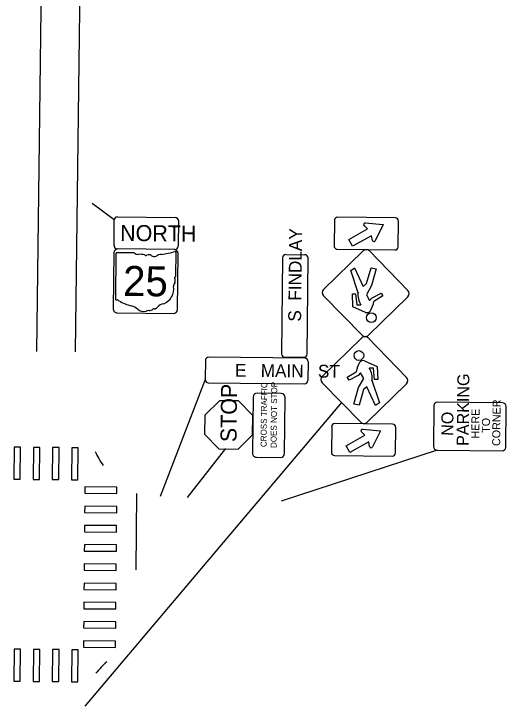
# Model space of a CAD drawing. Extents: x 1652376 to 1652707, y 605933 to 608571.
# Drawn here: x 1652553.2 to 1652706.7, y 606825.9 to 607041.8 of the extents above; entities that cross this region are included whole.
import ezdxf

# ---------------------------------------------------------------- set-up
doc = ezdxf.new("R2010")
doc.units = 0
for name, color, linetype in [('_CIVIL_CONSTRUCTION', 7, 'Continuous'), ('GE_P_Alignment', 7, 'Continuous'), ('PM_P_CL_Double_Solid', 7, 'Continuous'), ('SH_Border', 7, 'Continuous'), ('SN_X_Public', 7, 'Continuous'), ('UT_X_Misc_Cells', 7, 'Continuous')]:
    doc.layers.add(name, color=color, linetype=linetype)

msp = doc.modelspace()

# ---------------------------------------------------------------- linework, layer by layer
at = {"layer": '_CIVIL_CONSTRUCTION'}
for points in [[(1652553.24, 606896.7), (1652555.24, 606896.68), (1652555.33, 606906.68), (1652553.33, 606906.7)], [(1652559.24, 606896.65), (1652561.24, 606896.63), (1652561.33, 606906.63), (1652559.33, 606906.64)], [(1652565.24, 606896.59), (1652567.24, 606896.58), (1652567.33, 606906.58), (1652565.33, 606906.59)], [(1652571.24, 606896.54), (1652573.24, 606896.53), (1652573.33, 606906.53), (1652571.33, 606906.54)], [(1652575.38, 606894.32), (1652575.37, 606892.32), (1652585.37, 606892.23), (1652585.38, 606894.23)], [(1652575.33, 606888.32), (1652575.32, 606886.32), (1652585.32, 606886.23), (1652585.33, 606888.23)], [(1652575.33, 606888.32), (1652575.32, 606886.32), (1652585.32, 606886.23), (1652585.33, 606888.23)], [(1652575.28, 606882.32), (1652575.27, 606880.32), (1652585.27, 606880.23), (1652585.28, 606882.23)], [(1652575.23, 606876.32), (1652575.21, 606874.32), (1652585.21, 606874.23), (1652585.23, 606876.23)], [(1652575.18, 606870.32), (1652575.16, 606868.32), (1652585.16, 606868.24), (1652585.18, 606870.24)], [(1652575.13, 606864.32), (1652575.11, 606862.32), (1652585.11, 606862.24), (1652585.13, 606864.24)], [(1652575.08, 606858.32), (1652575.06, 606856.32), (1652585.06, 606856.24), (1652585.08, 606858.24)], [(1652575.03, 606852.32), (1652575.01, 606850.32), (1652585.01, 606850.24), (1652585.03, 606852.24)], [(1652574.98, 606846.32), (1652574.96, 606844.32), (1652584.96, 606844.24), (1652584.98, 606846.24)], [(1652553.24, 606833.7), (1652555.24, 606833.68), (1652555.33, 606843.68), (1652553.33, 606843.7)], [(1652559.24, 606833.65), (1652561.24, 606833.63), (1652561.33, 606843.63), (1652559.33, 606843.64)], [(1652565.24, 606833.59), (1652567.24, 606833.58), (1652567.33, 606843.58), (1652565.33, 606843.59)], [(1652571.24, 606833.54), (1652573.24, 606833.53), (1652573.33, 606843.53), (1652571.33, 606843.54)]]:
    msp.add_lwpolyline(points, close=True, dxfattribs=at)
at = {"layer": 'GE_P_Alignment'}
msp.add_lwpolyline([(1652560.46, 606936.56), (1652563.76, 607199.19), (1652564.08, 607225.34)], dxfattribs=at)
at = {"layer": 'PM_P_CL_Double_Solid'}
msp.add_lwpolyline([(1652572.46, 606936.42), (1652575.76, 607199.05), (1652576.07, 607225.19)], dxfattribs=at)
for centre, start, end in [((1652603.12, 606916.64), 204.7562, 215.3046), ((1652600.15, 606819.63), 131.6839, 142.1561)]:
    msp.add_arc(centre, 27, start, end, dxfattribs=at)
at = {"layer": 'SH_Border'}
for p, q in [((1652584.48, 606969.57), (1652584.57, 606977.57)), ((1652585.58, 606978.56), (1652603.58, 606978.36)), ((1652604.57, 606977.35), (1652604.48, 606969.35)), ((1652663.54, 606974.78), (1652662.45, 606975.79)), ((1652662.83, 606976.63), (1652662.83, 606976.63)), ((1652657.68, 606971.47), (1652663.54, 606974.78)), ((1652658.87, 606969.36), (1652657.68, 606971.47)), ((1652664.74, 606972.66), (1652658.87, 606969.36)), ((1652665.03, 606971.21), (1652664.74, 606972.66)), ((1652585.07, 606967.12), (1652584.91, 606952.89)), ((1652590.74, 606967.3), (1652585.25, 606967.36)), ((1652603.47, 606968.36), (1652585.47, 606968.56)), ((1652603.74, 606960.07), (1652603.82, 606967.51)), ((1652658.29, 606961.83), (1652659.49, 606962.68)), ((1652659.49, 606962.68), (1652662.2, 606956.85)), ((1652663.2, 606957.71), (1652664.64, 606962.63)), ((1652664.64, 606962.63), (1652666.22, 606962.32)), ((1652666.22, 606962.32), (1652664.78, 606957.11)), ((1652660.59, 606954.83), (1652658.29, 606961.83)), ((1652603.74, 606960.07), (1652603.74, 606960.07)), ((1652662.2, 606956.85), (1652663.2, 606957.71)), ((1652664.78, 606957.11), (1652663.16, 606954.22)), ((1652658.96, 606950.49), (1652658.81, 606954.56)), ((1652658.81, 606954.56), (1652659.8, 606954.55)), ((1652659.8, 606954.55), (1652660.15, 606951.06)), ((1652663.16, 606954.22), (1652664.13, 606952.47)), ((1652664.93, 606953.33), (1652667.72, 606954.75)), ((1652668.3, 606953.87), (1652665.51, 606952.16)), ((1652667.72, 606954.75), (1652668.3, 606953.87)), ((1652664.13, 606952.47), (1652664.93, 606953.33)), ((1652662.9, 606948.71), (1652658.96, 606950.49)), ((1652660.15, 606951.06), (1652661.46, 606951.05)), ((1652662.6, 606933.68), (1652666.54, 606931.89)), ((1652657.2, 606928.51), (1652659.99, 606930.23)), ((1652661.37, 606929.92), (1652660.57, 606929.06)), ((1652662.34, 606928.16), (1652661.37, 606929.92)), ((1652665.35, 606931.33), (1652664.04, 606931.34)), ((1652665.7, 606927.84), (1652665.35, 606931.33)), ((1652666.54, 606931.89), (1652666.69, 606927.83)), ((1652657.78, 606927.63), (1652657.2, 606928.51)), ((1652660.57, 606929.06), (1652657.78, 606927.63)), ((1652660.73, 606925.28), (1652662.34, 606928.16)), ((1652666.69, 606927.83), (1652665.7, 606927.84)), ((1652663.3, 606925.54), (1652662.3, 606924.68)), ((1652666.01, 606919.71), (1652663.3, 606925.54)), ((1652664.91, 606927.56), (1652667.21, 606920.56)), ((1652659.28, 606920.07), (1652660.73, 606925.28)), ((1652662.3, 606924.68), (1652660.86, 606919.76)), ((1652617.32, 606921.18), (1652612.77, 606916.73)), ((1652623.31, 606921.12), (1652617.32, 606921.18)), ((1652627.77, 606916.57), (1652623.31, 606921.12)), ((1652660.86, 606919.76), (1652659.28, 606920.07)), ((1652667.21, 606920.56), (1652666.01, 606919.71)), ((1652612.77, 606916.73), (1652612.7, 606910.73)), ((1652627.7, 606910.57), (1652627.77, 606916.57)), ((1652704.39, 606913.02), (1652704.39, 606913.02)), ((1652612.7, 606910.73), (1652617.15, 606906.18)), ((1652623.15, 606906.12), (1652627.7, 606910.57)), ((1652656.83, 606907.15), (1652662.69, 606910.46)), ((1652662.69, 606910.46), (1652661.6, 606911.46)), ((1652663.89, 606908.34), (1652658.02, 606905.04)), ((1652664.18, 606906.88), (1652663.89, 606908.34)), ((1652617.15, 606906.18), (1652623.15, 606906.12)), ((1652658.02, 606905.04), (1652656.83, 606907.15))]:
    msp.add_line(p, q, dxfattribs=at)
for points in [[(1652653.18, 606977.43), (1652653.1, 606969.43)], [(1652672.19, 606978.22), (1652654.19, 606978.42)], [(1652662.83, 606976.63), (1652668.44, 606976.14), (1652665.95, 606971.09)], [(1652673.09, 606969.21), (1652673.18, 606977.21)], [(1652584.46, 606967.32), (1652584.26, 606949.82)], [(1652603.22, 606968.36), (1652585.72, 606968.55)], [(1652604.26, 606949.6), (1652604.46, 606967.1)], [(1652638.02, 606966.79), (1652644.02, 606966.73)], [(1652649.82, 606955.89), (1652662.11, 606967.92)], [(1652654.09, 606968.42), (1652672.08, 606968.22)], [(1652664.09, 606967.9), (1652676.12, 606955.6)], [(1652637.01, 606965.81), (1652636.68, 606935.81)], [(1652644.68, 606935.72), (1652645.01, 606965.72)], [(1652661.82, 606941.62), (1652649.8, 606953.91)], [(1652676.1, 606953.62), (1652663.8, 606941.59)], [(1652585.5, 606948.56), (1652603, 606948.36)], [(1652649.4, 606928.77), (1652661.7, 606940.79)], [(1652663.68, 606940.77), (1652675.71, 606928.48)], [(1652643.97, 606934.46), (1652613.97, 606934.79)], [(1652637.67, 606934.8), (1652643.67, 606934.73)], [(1652612.96, 606933.8), (1652612.89, 606927.8)], [(1652644.96, 606933.45), (1652644.89, 606927.45)], [(1652613.88, 606926.79), (1652643.88, 606926.46)], [(1652661.41, 606914.49), (1652649.38, 606926.79)], [(1652675.68, 606926.5), (1652663.39, 606914.47)], [(1652636.59, 606923.47), (1652629.09, 606923.55)], [(1652627.83, 606922.32), (1652627.64, 606904.82)], [(1652637.64, 606904.71), (1652637.83, 606922.21)], [(1652684.24, 606919.65), (1652684.1, 606906.9)], [(1652705.63, 606920.54), (1652685.38, 606920.76)], [(1652706.6, 606906.65), (1652706.74, 606919.4)], [(1652652.34, 606913.11), (1652652.25, 606905.11)], [(1652671.35, 606913.9), (1652653.35, 606914.09)], [(1652672.25, 606904.89), (1652672.33, 606912.89)], [(1652661.98, 606912.31), (1652667.6, 606911.82), (1652665.1, 606906.77)], [(1652653.24, 606904.1), (1652671.24, 606903.9)], [(1652685.21, 606905.76), (1652705.46, 606905.54)], [(1652628.87, 606903.55), (1652636.37, 606903.47)]]:
    msp.add_lwpolyline(points, dxfattribs=at)
for centre in [(1652664.68, 606947.1), (1652660.82, 606935.29)]:
    msp.add_circle(centre, 1.52, dxfattribs=at)
for centre, radius, start, end in [((1652585.57, 606977.56), 1, 89.3709, 179.3709), ((1652603.57, 606977.36), 1, 359.3709, 89.3709), ((1652654.18, 606977.42), 1, 89.3709, 179.3709), ((1652672.18, 606977.22), 1, 359.3709, 89.3709), ((1652662.78, 606976.14), 0.486, 85.0472, 227.1837), ((1652665.51, 606971.3), 0.486, 191.5581, 333.6946), ((1652585.48, 606969.56), 1, 179.3709, 269.3709), ((1652603.48, 606969.36), 1, 269.3709, 359.3709), ((1652654.09, 606969.42), 1, 179.3709, 269.3709), ((1652672.09, 606969.22), 1, 269.3709, 359.3709), ((1652585.71, 606967.3), 1.25, 89.3709, 179.3709), ((1652585.28, 606967.15), 0.217, 97.501, 187.501), ((1652592.07, 606968.94), 2.11, 230.9904, 270.4828), ((1652592.66, 606959.29), 7.56, 79.8576, 94.3592), ((1652594.46, 606967.12), 0.608, 219.163, 296.4733), ((1652595.34, 606965.47), 1.26, 53.8376, 118.512), ((1652599.63, 606962.86), 4, 96.7171, 120.1397), ((1652597.35, 606986.63), 19.88, 275.2154, 288.2773), ((1652603.21, 606967.11), 1.25, 359.3709, 89.3709), ((1652603.61, 606967.54), 0.209, 351.233, 97.1089), ((1652638.01, 606965.79), 1, 89.3709, 179.3709), ((1652644.01, 606965.73), 1, 359.3709, 89.3709), ((1652663.09, 606966.92), 1.4, 44.3709, 134.3709), ((1652596.99, 606967.7), 1.52, 233.2271, 294.1991), ((1652603.68, 606959.52), 0.323, 107.3149, 209.7079), ((1652601.62, 606958.6), 1.94, 339.4039, 23.0205), ((1652603.52, 606960.04), 0.223, 288.9747, 7.105), ((1652598.13, 606956.07), 4.97, 291.6798, 8.3567), ((1652604.45, 606956.94), 1.41, 136.1774, 186.3005), ((1652650.8, 606954.89), 1.4, 134.3709, 224.3709), ((1652666.17, 606954.16), 5.64, 171.2211, 213.4318), ((1652675.12, 606954.62), 1.4, 314.3709, 44.3709), ((1652585.13, 606952.86), 0.219, 171.3293, 257.6775), ((1652585.17, 606954.31), 1.67, 266.7099, 279.9748), ((1652585.49, 606952.06), 0.603, 29.1193, 92.6426), ((1652593.25, 606964.76), 14.36, 239.7838, 256.5694), ((1652655.98, 606953.95), 9.69, 330.912, 349.4026), ((1652585.51, 606949.81), 1.25, 179.3709, 269.3709), ((1652588.76, 606946.45), 4.49, 46.5551, 75.2069), ((1652593.68, 606951.9), 2.85, 230.0713, 285.6627), ((1652595.28, 606946.96), 2.34, 85.066, 110.5808), ((1652595.53, 606950.82), 1.52, 268.1479, 314.9202), ((1652596.88, 606949.42), 0.428, 65.1226, 132.0193), ((1652596.72, 606951.38), 1.61, 282.2441, 322.648), ((1652600.15, 606948.73), 2.72, 93.774, 141.9476), ((1652603.01, 606949.61), 1.25, 269.3709, 359.3709), ((1652663.27, 606950.16), 1.5, 255.615, 321.8659), ((1652662.68, 606939.79), 1.4, 44.3709, 134.3709), ((1652662.82, 606942.6), 1.4, 224.3709, 314.3709), ((1652613.96, 606933.79), 1, 89.3709, 179.3709), ((1652637.68, 606935.8), 1, 179.3709, 269.3709), ((1652643.68, 606935.73), 1, 269.3709, 359.3709), ((1652643.96, 606933.46), 1, 359.3709, 89.3709), ((1652669.52, 606928.44), 9.69, 150.912, 169.4026), ((1652662.23, 606932.23), 1.5, 75.615, 141.8659), ((1652659.33, 606928.23), 5.64, 351.2211, 33.4318), ((1652613.89, 606927.79), 1, 179.3709, 269.3709), ((1652650.38, 606927.77), 1.4, 134.3709, 224.3709), ((1652674.71, 606927.5), 1.4, 314.3709, 44.3709), ((1652643.89, 606927.46), 1, 269.3709, 359.3709), ((1652629.08, 606922.3), 1.25, 89.3709, 179.3709), ((1652636.58, 606922.22), 1.25, 359.3709, 89.3709), ((1652685.36, 606919.63), 1.12, 89.3709, 179.3709), ((1652705.61, 606919.41), 1.12, 359.3709, 89.3709), ((1652653.33, 606913.09), 1, 89.3709, 179.3709), ((1652662.41, 606915.47), 1.4, 224.3709, 314.3709), ((1652671.33, 606912.9), 1, 359.3709, 89.3709), ((1652661.94, 606911.82), 0.486, 85.0472, 227.1837), ((1652664.66, 606906.98), 0.486, 191.5581, 333.6946), ((1652685.22, 606906.88), 1.12, 179.3709, 269.3709), ((1652705.47, 606906.66), 1.12, 269.3709, 359.3709), ((1652628.89, 606904.8), 1.25, 179.3709, 269.3709), ((1652636.39, 606904.72), 1.25, 269.3709, 359.3709), ((1652653.25, 606905.1), 1, 179.3709, 269.3709), ((1652671.25, 606904.9), 1, 269.3709, 359.3709)]:
    msp.add_arc(centre, radius, start, end, dxfattribs=at)
at = {"layer": 'SN_X_Public'}
msp.add_line((1652591.4, 606868.48), (1652591.6, 606892.22), dxfattribs=at)
at = {"layer": 'UT_X_Misc_Cells'}
for p, q in [((1652584.57, 606977.57), (1652577.61, 606982.65)), ((1652612.89, 606927.8), (1652598.84, 606891.28)), ((1652655.4, 606920.64), (1652575.39, 606825.94)), ((1652619.22, 606906.33), (1652607.29, 606891)), ((1652685.21, 606905.76), (1652636.59, 606889.83))]:
    msp.add_line(p, q, dxfattribs=at)

# ---------------------------------------------------------------- texts
at = {"layer": 'SH_Border'}
for s, height, rotation, p in [('NORTH', 5, 359.3709, (1652586.36, 606971.05)), ('        S  FINDLAY', 4, 89.3709, (1652642.66, 606933.95)), ('25', 9.375, 359.3709, (1652587.26, 606953.87)), ('        E   MAIN   ST', 4, 359.3709, (1652610.29, 606928.83)), ('PARKING', 3.75, 89.3709, (1652695.04, 606907.09)), ('STOP', 5, 89.3709, (1652622.67, 606908.25)), ('CROSS TRAFFIC', 1.875, 89.3709, (1652632.03, 606906.73)), ('DOES NOT STOP', 1.875, 89.3709, (1652635.15, 606906.44)), ('CORNER', 2.5, 89.3709, (1652704.88, 606907.07)), ('NO', 3.75, 89.3709, (1652690.23, 606910.23)), ('HERE', 2.5, 89.3709, (1652698.35, 606909.41)), ('TO', 2.5, 89.3709, (1652701.65, 606911.18))]:
    msp.add_text(s, height=height, rotation=rotation, dxfattribs=at).set_placement(p)

doc.saveas('drawing.dxf')
